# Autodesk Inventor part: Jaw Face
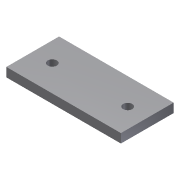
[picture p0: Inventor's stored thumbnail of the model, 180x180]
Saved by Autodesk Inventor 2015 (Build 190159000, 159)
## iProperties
Shininess: 77.0
Length Units: 11269
Angle Units: 11279
Time Units: 11290
Mass Units: 11283
Length Display Precision: 3
Angle Display Precision: 2
Compacted: True
Created: 2002-02
Part Number: Jaw Face
Document SubType Name: Modeling
Designer: ***
Density: 1 g/cm^3
Material: Generic
Appearance: Default
Density: 0.0
Volumn: 0.0
Area: 0.0
PropertySet Name: Model Information
Control State: 0
Master: False
Checked Out: False
Author: ***
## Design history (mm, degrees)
sketch "Sketch1"
  geometry: L1 (-79.661, -8.43)-(-3.661, -8.43); L2 (-3.661, -8.43)-(-3.661, -43.43); L3 (-3.661, -43.43)-(-79.661, -43.43); L4 (-79.661, -43.43)-(-79.661, -8.43); C1 r 3 at (-66.661, -25.93); C2 r 3 at (-16.661, -25.93)
  constraints: 8 end point, 2 centre point, 2 parallel, 1 equal radius, 1 horizontal, 1 perpendicular
  dimensions: "d0" = 76 distance of L2.end L3.end; "d1" = 6 diameter of C1; "d2" = 50 distance of C2.centre C1.centre; "d3" = 35 distance of L1.end L2.end; "d4" = 17.5 distance from line of L3 C2.centre; "d5" = 13 distance from line of L2 C2.centre; "d6" = 13 distance from line of L4 C1.centre
extrude "Extrusion1" new body sketch "Sketch1" stored distance "d7" = 6; taper "d8" = 0 deg
body "Solid1"
